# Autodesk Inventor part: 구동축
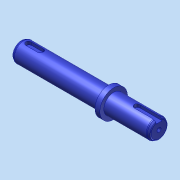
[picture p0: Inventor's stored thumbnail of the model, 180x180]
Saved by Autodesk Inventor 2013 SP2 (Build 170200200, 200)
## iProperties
Created: 2026-01
Part Number: 구동축
Material: Generic
Document SubType Name: Modeling
Designer: a
Density: 1 g/cm^3
Author: a
변환 표준: STEP AP214IS
전처리기: Build: 200, Release: 2013 SP2 Update 6 - Date: Thu 07/17/2014
전송 단위: 밀리미터
불확실성: 0.01
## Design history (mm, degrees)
node "구동축1"
node "솔리드1"
node "기준1"
